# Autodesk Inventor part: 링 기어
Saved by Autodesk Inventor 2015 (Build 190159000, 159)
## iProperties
Created: 2026-05
Part Number: 링 기어
Material: 일반
Document SubType Name: Modeling
Designer: 104
Density: 1 g/cm^3
Appearance: 기본값
Author: 104
Author: jhkim
Creation Date: 2026-04-27
Sending System: Autodesk Inventor 2027
Preprocessor: ST-DEVELOPER v20.1
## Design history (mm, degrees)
node "링 기어1"
node "솔리드1"
node "기준1"
